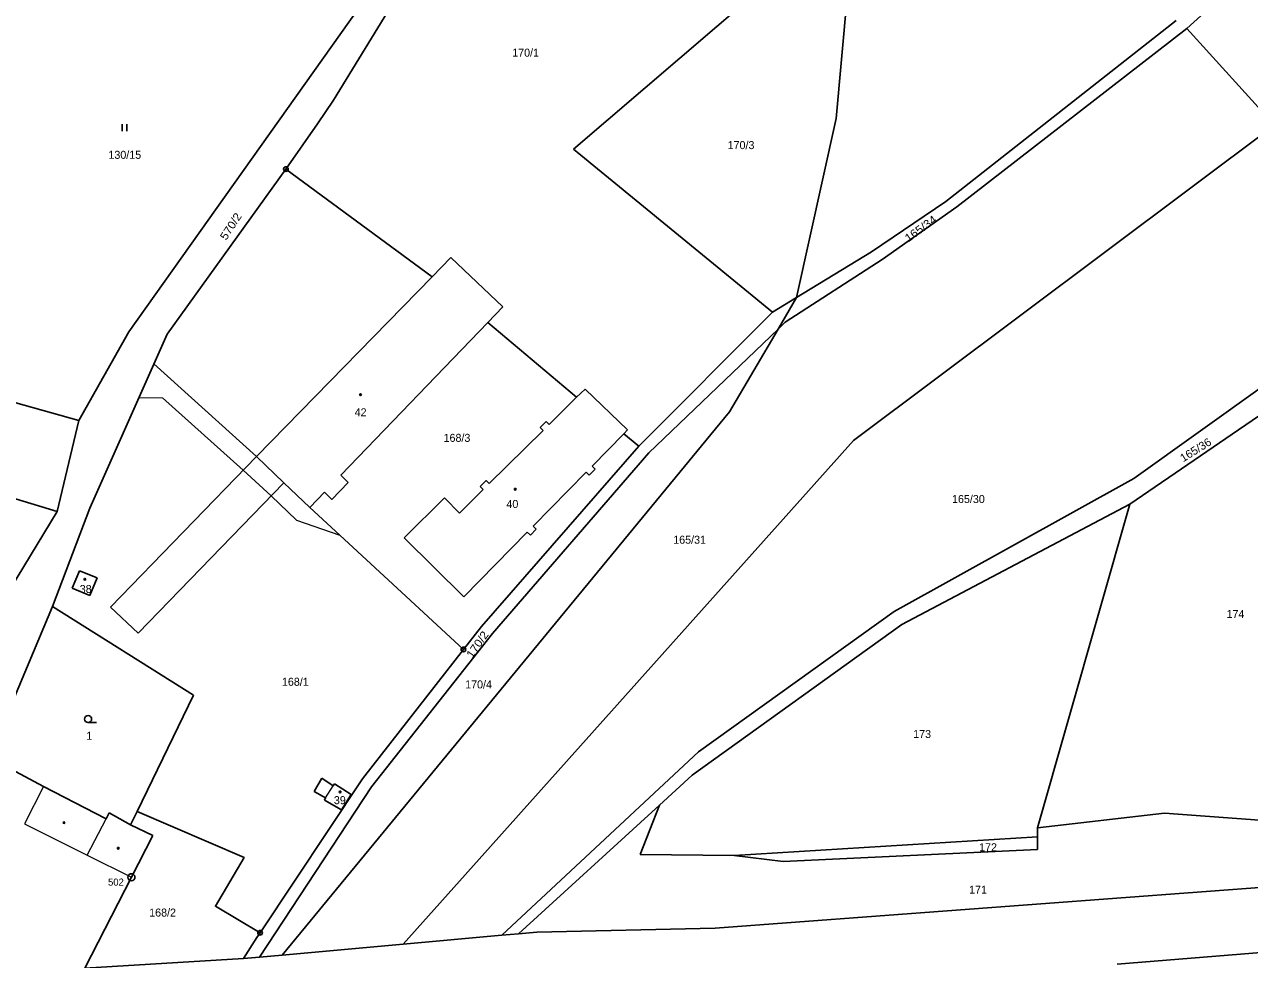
# Model space of a CAD drawing. Extents: x -664548 to -662415, y -1069720 to -1068208.
# Drawn here: x -663493.9 to -663233.8, y -1068905.8 to -1068707.2 of the extents above; entities that cross this region are included whole.
import ezdxf
from ezdxf.enums import TextEntityAlignment as Align

# ---------------------------------------------------------------- set-up
doc = ezdxf.new("R2010")
doc.units = 0
doc.header["$LTSCALE"] = 0.68
for name, color, linetype, lineweight in [('1', 7, 'Continuous', 25), ('13', 7, 'Continuous', 13), ('3', 7, 'Continuous', 25), ('4', 7, 'Continuous', 13), ('5', 7, 'Continuous', 25), ('8', 7, 'Continuous', 25)]:
    doc.layers.add(name, color=color, linetype=linetype, lineweight=lineweight)
doc.layers.add('2', color=7, linetype='Continuous')

msp = doc.modelspace()

# ---------------------------------------------------------------- linework, layer by layer
at = {"layer": '1'}
for p, q in [((-663428.3, -1068723.28), (-663401.57, -1068679.64)), ((-663247.14, -1068708.08), (-663215.58, -1068679.48)), ((-663327.75, -1068691.25), (-663377.32, -1068733.7)), ((-663420.62, -1068700.44), (-663471.78, -1068772.5)), ((-663318.99, -1068698.86), (-663321.58, -1068727.2)), ((-663298.31, -1068744.83), (-663249.36, -1068706.4)), ((-663295.92, -1068745.92), (-663247.14, -1068708.08)), ((-663247.14, -1068708.08), (-663228.48, -1068728.63)), ((-663431.74, -1068728.31), (-663428.3, -1068723.28)), ((-663438.42, -1068737.95), (-663431.74, -1068728.31)), ((-663321.58, -1068727.2), (-663329.97, -1068765.21)), ((-663317.89, -1068795.6), (-663228.48, -1068728.63)), ((-663377.32, -1068733.7), (-663335.1, -1068768.34)), ((-663438.42, -1068737.95), (-663463.65, -1068773)), ((-663407.33, -1068760.82), (-663438.42, -1068737.95)), ((-663314.1, -1068755.53), (-663298.31, -1068744.83)), ((-663311.77, -1068757.12), (-663295.92, -1068745.92)), ((-663403.36, -1068756.73), (-663407.33, -1068760.82)), ((-663392.33, -1068767.22), (-663403.36, -1068756.73)), ((-663332.4, -1068770.47), (-663311.77, -1068757.12)), ((-663329.97, -1068765.21), (-663314.1, -1068755.53)), ((-663407.33, -1068760.82), (-663444.64, -1068798.93)), ((-663335.1, -1068768.34), (-663329.97, -1068765.21)), ((-663329.97, -1068765.21), (-663333.89, -1068771.9)), ((-663395.53, -1068770.53), (-663392.33, -1068767.22)), ((-663426.74, -1068802.94), (-663395.53, -1068770.53)), ((-663376.73, -1068786.4), (-663395.53, -1068770.53)), ((-663335.1, -1068768.34), (-663363.44, -1068796.78)), ((-663332.4, -1068770.47), (-663333.89, -1068771.9)), ((-663471.78, -1068772.5), (-663482.4, -1068791.3)), ((-663463.65, -1068773), (-663480.04, -1068809.93)), ((-663333.89, -1068771.9), (-663361.33, -1068798.2)), ((-663333.89, -1068771.9), (-663344.2, -1068789.48)), ((-663482.4, -1068791.3), (-663513.3, -1068782.72)), ((-663258.34, -1068803.65), (-663230.57, -1068783.74)), ((-663382.53, -1068792.18), (-663376.73, -1068786.4)), ((-663374.9, -1068784.65), (-663376.73, -1068786.4)), ((-663365.9, -1068793.32), (-663374.9, -1068784.65)), ((-663226.21, -1068786.49), (-663259.22, -1068809.05)), ((-663482.4, -1068791.3), (-663487, -1068810.65)), ((-663344.2, -1068789.48), (-663439.19, -1068904.81)), ((-663384.45, -1068792.8), (-663383.17, -1068791.54)), ((-663383.17, -1068791.54), (-663382.53, -1068792.18)), ((-663395.23, -1068804.7), (-663383.82, -1068793.45)), ((-663383.82, -1068793.45), (-663384.45, -1068792.8)), ((-663366.66, -1068794.16), (-663373.41, -1068800.99)), ((-663365.9, -1068793.32), (-663366.66, -1068794.16)), ((-663363.44, -1068796.78), (-663366.66, -1068794.16)), ((-663413.5, -1068902.5), (-663317.89, -1068795.6)), ((-663363.44, -1068796.78), (-663396.9, -1068835.07)), ((-663487, -1068810.65), (-663527.36, -1068798.44)), ((-663438.84, -1068804.52), (-663444.64, -1068798.93)), ((-663361.33, -1068798.2), (-663394.53, -1068836.53)), ((-663372.76, -1068801.62), (-663374.02, -1068802.91)), ((-663373.41, -1068800.99), (-663372.76, -1068801.62)), ((-663438.84, -1068804.52), (-663433.35, -1068809.8)), ((-663426.74, -1068802.94), (-663425.16, -1068804.46)), ((-663374.67, -1068802.28), (-663385.89, -1068813.74)), ((-663374.02, -1068802.91), (-663374.67, -1068802.28)), ((-663309.25, -1068831.88), (-663258.34, -1068803.65)), ((-663430.23, -1068806.57), (-663433.35, -1068809.8)), ((-663401.58, -1068810.97), (-663396.51, -1068805.97)), ((-663396.51, -1068805.97), (-663397.15, -1068805.33)), ((-663487.98, -1068830.84), (-663480.04, -1068809.93)), ((-663413.31, -1068816.2), (-663404.75, -1068807.76)), ((-663404.75, -1068807.76), (-663401.58, -1068810.97)), ((-663259.22, -1068809.05), (-663307.61, -1068834.61)), ((-663259.22, -1068809.05), (-663278.79, -1068877.82)), ((-663496.86, -1068827.02), (-663487, -1068810.65)), ((-663387.15, -1068815.03), (-663400.62, -1068828.79)), ((-663386.51, -1068815.66), (-663387.15, -1068815.03)), ((-663385.25, -1068814.37), (-663386.51, -1068815.66)), ((-663385.89, -1068813.74), (-663385.25, -1068814.37)), ((-663400.62, -1068828.79), (-663413.31, -1068816.2)), ((-663483.77, -1068826.89), (-663482.23, -1068823.21)), ((-663482.23, -1068823.21), (-663478.46, -1068824.76)), ((-663478.46, -1068824.76), (-663480.03, -1068828.48)), ((-663480.03, -1068828.48), (-663483.77, -1068826.89)), ((-663496.98, -1068852.29), (-663487.98, -1068830.84)), ((-663458.07, -1068849.61), (-663487.98, -1068830.84)), ((-663350.81, -1068861.68), (-663309.25, -1068831.88)), ((-663396.9, -1068835.07), (-663400.71, -1068839.94)), ((-663307.61, -1068834.61), (-663352.13, -1068866.63)), ((-663394.53, -1068836.53), (-663420.25, -1068869.1)), ((-663400.71, -1068839.94), (-663422.17, -1068867.42)), ((-663470.03, -1068874.37), (-663458.07, -1068849.61)), ((-663392.54, -1068900.62), (-663350.81, -1068861.68)), ((-663502.03, -1068862.59), (-663489.86, -1068869.05)), ((-663359.08, -1068872.98), (-663352.13, -1068866.63)), ((-663489.86, -1068869.05), (-663476.6, -1068875.89)), ((-663420.25, -1068869.1), (-663444.05, -1068905.25)), ((-663422.17, -1068867.42), (-663443.9, -1068900.08)), ((-663432.41, -1068870.08), (-663430.78, -1068867.24)), ((-663430.78, -1068867.24), (-663428.36, -1068868.89)), ((-663428.08, -1068868.48), (-663428.36, -1068868.89)), ((-663428.08, -1068868.48), (-663424.59, -1068870.73)), ((-663429.98, -1068871.47), (-663432.41, -1068870.08)), ((-663430.23, -1068871.91), (-663429.98, -1068871.47)), ((-663426.59, -1068874), (-663430.23, -1068871.91)), ((-663426.59, -1068874), (-663424.59, -1068870.73)), ((-663476.6, -1068875.89), (-663475.96, -1068874.62)), ((-663475.96, -1068874.62), (-663471.39, -1068877.19)), ((-663471.39, -1068877.19), (-663470.03, -1068874.37)), ((-663389.01, -1068900.3), (-663359.08, -1068872.98)), ((-663363.22, -1068883.46), (-663359.08, -1068872.98)), ((-663278.79, -1068877.82), (-663251.85, -1068874.7)), ((-663251.85, -1068874.7), (-663225.45, -1068876.61)), ((-663471.39, -1068877.19), (-663466.66, -1068879.43)), ((-663466.66, -1068879.43), (-663471.21, -1068888.3)), ((-663343.25, -1068883.69), (-663278.79, -1068879.71)), ((-663278.79, -1068877.82), (-663278.79, -1068879.71)), ((-663278.79, -1068879.71), (-663278.79, -1068882.41)), ((-663278.79, -1068882.41), (-663332.8, -1068884.95)), ((-663343.25, -1068883.69), (-663363.22, -1068883.46)), ((-663332.8, -1068884.95), (-663343.25, -1068883.69)), ((-663347.26, -1068899.14), (-663196.6, -1068887.88)), ((-663481.1, -1068907.57), (-663471.21, -1068888.3)), ((-663443.9, -1068900.08), (-663444.58, -1068901.1)), ((-663392.54, -1068900.62), (-663413.5, -1068902.5)), ((-663389.01, -1068900.3), (-663392.54, -1068900.62)), ((-663385.11, -1068899.95), (-663389.01, -1068900.3)), ((-663385.11, -1068899.95), (-663347.26, -1068899.14)), ((-663444.58, -1068901.1), (-663447.39, -1068905.55)), ((-663413.5, -1068902.5), (-663439.19, -1068904.81)), ((-663481.1, -1068907.57), (-663447.39, -1068905.55)), ((-663444.05, -1068905.25), (-663447.39, -1068905.55)), ((-663439.19, -1068904.81), (-663444.05, -1068905.25)), ((-663227.49, -1068903.95), (-663261.93, -1068906.77))]:
    msp.add_line(p, q, dxfattribs=at)
for points in [[(-663425.16, -1068804.46), (-663428.65, -1068808.09), (-663430.23, -1068806.57)], [(-663397.15, -1068805.33), (-663395.86, -1068804.06), (-663395.23, -1068804.7)], [(-663433.35, -1068809.8), (-663426.97, -1068815.69), (-663400.71, -1068839.94)], [(-663470.03, -1068874.37), (-663447.28, -1068884.14), (-663453.39, -1068894.44), (-663443.9, -1068900.08)]]:
    msp.add_lwpolyline(points, dxfattribs=at)
at = {"layer": '13'}
msp.add_lwpolyline([(-663466.45, -1068779.31), (-663469.61, -1068786.44), (-663464.64, -1068786.51), (-663447.52, -1068801.9), (-663441.55, -1068807.32), (-663436.15, -1068812.5), (-663426.97, -1068815.69), (-663433.35, -1068809.8), (-663438.84, -1068804.52), (-663444.64, -1068798.93)], close=True, dxfattribs=at)
at = {"layer": '3'}
for p, q in [((-663473.171, -1068729.88), (-663473.171, -1068728.38)), ((-663472.17, -1068729.88), (-663472.17, -1068728.38)), ((-663480.413, -1068855.46), (-663478.663, -1068855.46))]:
    msp.add_line(p, q, dxfattribs=at)
msp.add_circle((-663480.4129, -1068854.7098), 0.75, dxfattribs=at)
at = {"layer": '4'}
for p, q in [((-663444.64, -1068798.93), (-663475.65, -1068830.93)), ((-663438.84, -1068804.52), (-663469.75, -1068836.45)), ((-663475.65, -1068830.93), (-663469.75, -1068836.45)), ((-663489.86, -1068869.05), (-663493.9, -1068876.99)), ((-663429.98, -1068871.47), (-663428.36, -1068868.89)), ((-663493.9, -1068876.99), (-663480.6, -1068883.62)), ((-663480.6, -1068883.62), (-663476.6, -1068875.89)), ((-663480.6, -1068883.62), (-663471.21, -1068888.3))]:
    msp.add_line(p, q, dxfattribs=at)
at = {"layer": '5'}
for centre in [(-663422.5668, -1068785.8192), (-663389.7168, -1068805.9092), (-663481.0968, -1068825.0392), (-663426.9068, -1068870.1792), (-663485.5368, -1068876.7092), (-663474.0268, -1068882.1392)]:
    msp.add_circle(centre, 0.175, dxfattribs=at)
at = {"layer": '8'}
for centre, radius in [((-663438.42, -1068737.9499), 0.5), ((-663438.42, -1068737.9499), 0.0303), ((-663400.71, -1068839.9399), 0.5), ((-663400.71, -1068839.9399), 0.0303), ((-663471.21, -1068888.2998), 0.75), ((-663471.21, -1068888.2998), 0.03), ((-663443.9, -1068900.0799), 0.5), ((-663443.9, -1068900.0799), 0.0303)]:
    msp.add_circle(centre, radius, dxfattribs=at)

# ---------------------------------------------------------------- texts
at = {"layer": '2'}
for s, p in [('170/1', (-663390.36, -1068714.074)), ('130/15', (-663476.1, -1068735.755)), ('170/3', (-663344.62, -1068733.695)), ('42', (-663423.82, -1068790.425)), ('165/30', (-663296.97, -1068808.844)), ('40', (-663391.59, -1068809.895)), ('165/31', (-663356.17, -1068817.485)), ('38', (-663482.19, -1068827.935)), ('174', (-663238.68, -1068833.255)), ('170/4', (-663400.35, -1068848.205)), ('1', (-663480.79, -1068859.115)), ('173', (-663305.22, -1068858.735)), ('39', (-663428.23, -1068872.785)), ('172', (-663291.22, -1068882.775)), ('171', (-663293.34, -1068891.785))]:
    msp.add_text(s, height=1.7, dxfattribs=at).set_placement(p)
for s, rotation, width, p in [('570/2', 57, 1.1, (-663451.103, -1068753.181)), ('165/34', 36, 1.1, (-663306.23, -1068753.513)), ('165/36', 32, 1.05, (-663247.884, -1068800.21)), ('170/2', 55, 1.1, (-663398.851, -1068841.923))]:
    msp.add_text(s, height=1.7, rotation=rotation, dxfattribs=dict(at, width=width)).set_placement(p)
for s, p in [('168/3', (-663402.09, -1068795.854)), ('168/1', (-663436.41, -1068847.645)), ('168/2', (-663464.6, -1068896.645))]:
    msp.add_text(s, height=1.7, dxfattribs=at).set_placement(p, align=Align.CENTER)
at = {"layer": '8'}
msp.add_text('502', height=1.5, dxfattribs=at).set_placement((-663472.829, -1068890.077), align=Align.RIGHT)

doc.saveas('drawing.dxf')
